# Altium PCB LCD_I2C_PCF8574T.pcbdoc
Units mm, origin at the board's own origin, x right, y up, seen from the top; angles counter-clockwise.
Board outline 54.7 x 31.7 mm, 2 copper layers (Top Layer, Bottom Layer), stack 0.071 mm thick; 1 components, 0 nets, 20 pads, 0 vias.
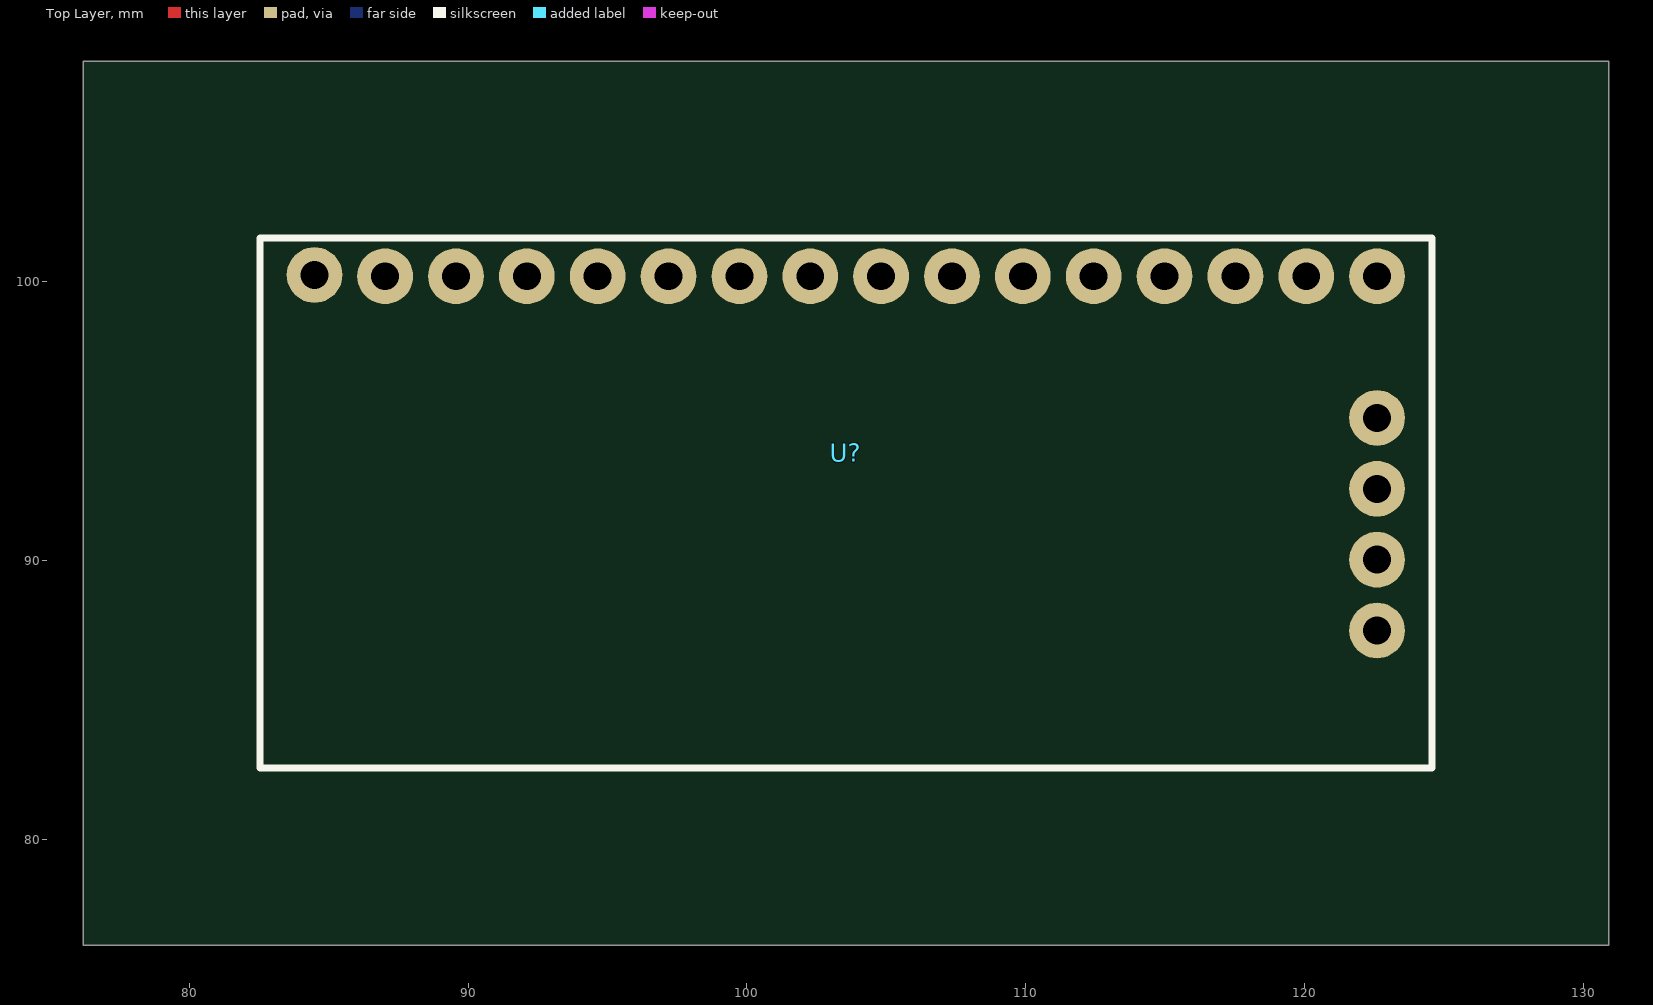
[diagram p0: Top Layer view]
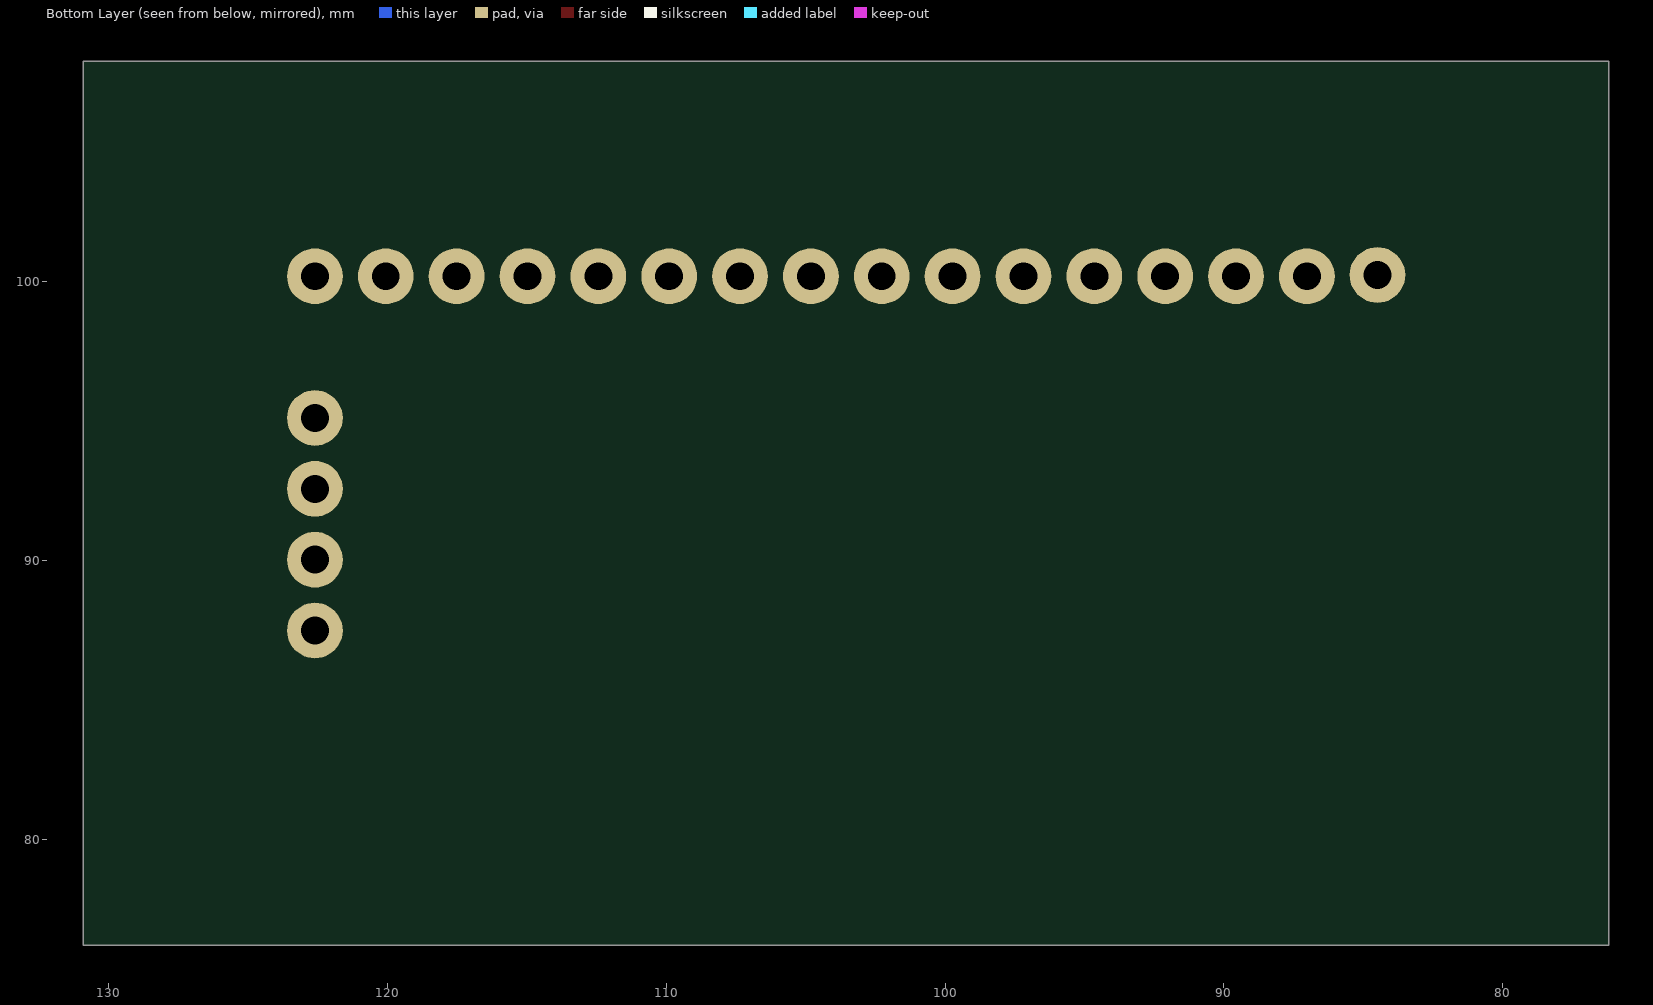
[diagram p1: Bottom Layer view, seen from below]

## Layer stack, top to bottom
Top Solder Mask Layer: solder mask 0.0102, Dk 3.3
Top Layer: signal copper 0.0356
Bottom Layer: signal copper 0.0356
Bottom Solder Mask Layer: solder mask 0.0102, Dk 3.3

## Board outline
130.899,107.899 130.899,76.2 76.2,76.2 76.2,107.899

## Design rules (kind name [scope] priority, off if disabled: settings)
BoardOutlineClearance copperThickness1oz [All] p0: genericclearance=0.254 ignorepadtopadclearanceinfootprint=FALSE except(0: Arc-SplitContinuation Track-SplitContinuation SMDPad-SplitContinuation THPad-SplitContinuation Via-SplitContinuation Fill-SplitContinuation Poly-SplitContinuation Region-SplitContinuation Text-SplitContinuation)
BoardOutlineClearance otherClearance [All] p0: genericclearance=0.254 ignorepadtopadclearanceinfootprint=FALSE except(0: Arc-SplitContinuation Track-SplitContinuation SMDPad-SplitContinuation THPad-SplitContinuation Via-SplitContinuation Fill-SplitContinuation Poly-SplitContinuation Region-SplitContinuation Text-SplitContinuation)
Clearance copperThickness1oz [All] p1: gap=0.178 ignorepadtopadclearanceinfootprint=FALSE
Clearance otherClearance [All] p1: gap=0.178 ignorepadtopadclearanceinfootprint=FALSE
DiffPairsRouting differentialPair [All] p1: maxuncoupledlength=10 minlimit=5 maxlimit=Infinity mostfreqgap=6 toplayer_minwidth=5 toplayer_prefwidth=100 toplayer_maxwidth=100 bottomlayer_minwidth=5 bottomlayer_prefwidth=100 bottomlayer_maxwidth=100
PasteMaskExpansion pasteMaskExpansion [All] p1: expansion=0
PlaneConnect innerPlane [All] p1: planeconnectstyle=Relief reliefexpansion=0.508 reliefentries=4 reliefconductorwidth=0.254 reliefairgap=0.254
PolygonConnect copperRegion [All] p1: connectstyle=Relief reliefentries=4 reliefconductorwidth=10 polygonreliefangle="90 Angle" airgapwidth=10
RoutingVias viaSize [All] p1: viastyle="Through Hole" holewidth=24 minholewidth=19.7 maxholewidth=393.7 width=24 minwidth=19.7 maxwidth=393.7
SolderMaskExpansion solderMaskExpansion [IsVia] p1: useseparateexpansions=TRUE expansion=-1000 expansionbottom=-1000
SolderMaskExpansion solderMaskExpansion [All] p2: useseparateexpansions=TRUE expansion=2 expansionbottom=2
Width copperThickness1oz [All] p1: maxlimit=100 minlimit=5 preferedwidth=10

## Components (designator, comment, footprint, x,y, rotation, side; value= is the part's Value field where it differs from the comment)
U? "" "I2C MODULE" 73.185,91.549 r0 top

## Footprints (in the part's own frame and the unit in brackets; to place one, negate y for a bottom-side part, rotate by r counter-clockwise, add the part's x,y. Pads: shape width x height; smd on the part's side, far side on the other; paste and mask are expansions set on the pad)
"I2C MODULE" [mil]
  round 78.7 hole 39.4 paste+0 mask+4: A(545,340) D0(1345,340) D1(1245,340) D2(1145,340) D3(1045,340) D4(945,340) D5(845,340) D6(745,340) D7(645,340) E(1445,340) GND(1945,140) K(445.4,341.8) RS(1645,340) RW(1545,340) SCL(1945,-160) SDA(1945,-60) V0(1745,340) VCC(1945,40) VDD(1845,340) VSS(1945,340)
  silkscreen extent 369,-354 2022,394

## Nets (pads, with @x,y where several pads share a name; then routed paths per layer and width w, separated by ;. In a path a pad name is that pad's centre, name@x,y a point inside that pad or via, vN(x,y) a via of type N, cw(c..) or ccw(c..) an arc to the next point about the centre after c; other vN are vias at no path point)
pads on no net: U?.A U?.D0 U?.D1 U?.D2 U?.D3 U?.D4 U?.D5 U?.D6 U?.D7 U?.E U?.GND U?.K U?.RS U?.RW U?.SCL U?.SDA U?.V0 U?.VCC U?.VDD U?.VSS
